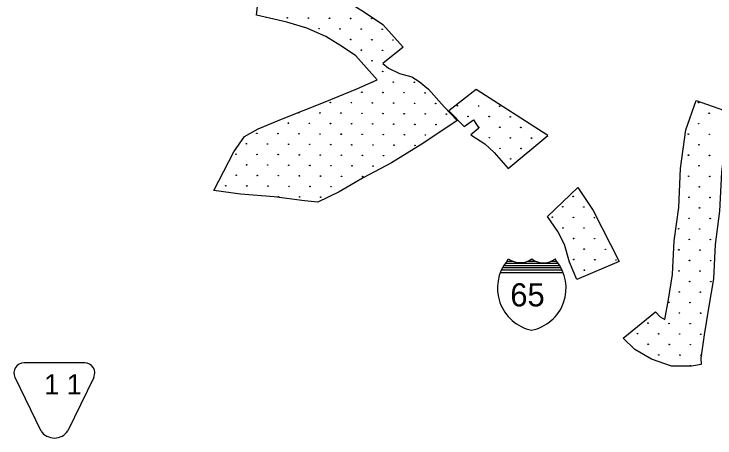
# Model space of a CAD drawing. Extents: x 1612280 to 1883141, y 560852 to 780851.
# Drawn here: x 1746855 to 1759645, y 710000 to 717744 of the extents above; entities that cross this region are included whole.
import ezdxf

# ---------------------------------------------------------------- set-up
doc = ezdxf.new("R2010")
doc.units = 0
for name, color, linetype in [('DESIGN - EROSION CONTROL - Devices', 7, 'Continuous'), ('DESIGN - ROW - Easement Linework and Patterning', 7, 'Continuous'), ('DESIGN - SCRATCH - User 1', 7, 'Continuous'), ('SURVEY - DRAINAGE - Bridge Hydraulic Data with Text', 7, 'Continuous')]:
    doc.layers.add(name, color=color, linetype=linetype)

msp = doc.modelspace()

# ---------------------------------------------------------------- linework, layer by layer
at = {"layer": 'DESIGN - EROSION CONTROL - Devices'}
for centre in [(1751842, 717674), (1751842, 717674), (1752227, 717670), (1752227, 717670), (1752611, 717666), (1752611, 717666), (1752996, 717662), (1752996, 717662), (1753380, 717659), (1753380, 717659), (1752421, 717476), (1752421, 717476), (1752805, 717472), (1752805, 717472), (1753190, 717468), (1753190, 717468), (1753574, 717465), (1753574, 717465), (1752999, 717278), (1752999, 717278), (1753384, 717274), (1753384, 717274), (1753768, 717270), (1753768, 717270), (1753194, 717084), (1753194, 717084), (1753578, 717080), (1753578, 717080), (1753388, 716890), (1753388, 716890), (1753582, 716695), (1753582, 716695), (1753776, 716501), (1753776, 716501), (1754161, 716498), (1754161, 716498), (1753201, 716315), (1753201, 716315), (1753586, 716311), (1753586, 716311), (1753970, 716307), (1753970, 716307), (1754355, 716303), (1754355, 716303), (1752626, 716128), (1752626, 716128), (1753011, 716124), (1753011, 716124), (1753395, 716120), (1753395, 716120), (1753780, 716117), (1753780, 716117), (1754164, 716113), (1754164, 716113), (1754549, 716109), (1754549, 716109), (1754946, 716068), (1754946, 716068), (1755331, 716064), (1755331, 716064), (1755715, 716060), (1755715, 716060), (1759345, 716125), (1759345, 716125), (1752051, 715941), (1752051, 715941), (1752436, 715938), (1752436, 715938), (1752820, 715934), (1752820, 715934), (1753205, 715930), (1753205, 715930), (1753589, 715926), (1753589, 715926), (1753974, 715923), (1753974, 715923), (1754358, 715919), (1754358, 715919), (1754743, 715915), (1754743, 715915), (1759539, 715931), (1759539, 715931), (1755140, 715873), (1755140, 715873), (1755525, 715870), (1755525, 715870), (1755909, 715866), (1755909, 715866), (1751861, 715751), (1751861, 715751), (1752245, 715747), (1752245, 715747), (1752630, 715743), (1752630, 715743), (1753014, 715740), (1753014, 715740), (1753399, 715736), (1753399, 715736), (1753783, 715732), (1753783, 715732), (1754168, 715728), (1754168, 715728), (1754553, 715725), (1754553, 715725), (1755334, 715679), (1755334, 715679), (1755719, 715676), (1755719, 715676), (1756103, 715672), (1756103, 715672), (1759348, 715741), (1759348, 715741), (1751286, 715564), (1751286, 715564), (1751670, 715560), (1751670, 715560), (1752055, 715557), (1752055, 715557), (1752439, 715553), (1752439, 715553), (1752824, 715549), (1752824, 715549), (1753208, 715546), (1753208, 715546), (1753593, 715542), (1753593, 715542), (1753978, 715538), (1753978, 715538), (1754362, 715534), (1754362, 715534), (1759158, 715550), (1759158, 715550), (1759542, 715546), (1759542, 715546), (1755528, 715485), (1755528, 715485), (1755913, 715481), (1755913, 715481), (1756298, 715478), (1756298, 715478), (1751095, 715374), (1751095, 715374), (1751480, 715370), (1751480, 715370), (1751864, 715366), (1751864, 715366), (1752249, 715363), (1752249, 715363), (1752634, 715359), (1752634, 715359), (1753018, 715355), (1753018, 715355), (1753403, 715351), (1753403, 715351), (1753787, 715348), (1753787, 715348), (1754172, 715344), (1754172, 715344), (1755723, 715291), (1755723, 715291), (1756107, 715287), (1756107, 715287), (1759352, 715356), (1759352, 715356), (1750905, 715183), (1750905, 715183), (1751289, 715180), (1751289, 715180), (1751674, 715176), (1751674, 715176), (1752059, 715172), (1752059, 715172), (1752443, 715168), (1752443, 715168), (1752828, 715165), (1752828, 715165), (1753212, 715161), (1753212, 715161), (1753597, 715157), (1753597, 715157), (1759162, 715166), (1759162, 715166), (1759546, 715162), (1759546, 715162), (1755917, 715097), (1755917, 715097), (1751099, 714989), (1751099, 714989), (1751484, 714986), (1751484, 714986), (1751868, 714982), (1751868, 714982), (1752253, 714978), (1752253, 714978), (1752637, 714974), (1752637, 714974), (1753022, 714971), (1753022, 714971), (1753406, 714967), (1753406, 714967), (1759356, 714972), (1759356, 714972), (1750909, 714799), (1750909, 714799), (1751293, 714795), (1751293, 714795), (1751678, 714791), (1751678, 714791), (1752062, 714788), (1752062, 714788), (1752447, 714784), (1752447, 714784), (1752831, 714780), (1752831, 714780), (1753216, 714776), (1753216, 714776), (1759165, 714781), (1759165, 714781), (1759550, 714777), (1759550, 714777), (1750718, 714608), (1750718, 714608), (1751103, 714605), (1751103, 714605), (1751487, 714601), (1751487, 714601), (1751872, 714597), (1751872, 714597), (1752256, 714593), (1752256, 714593), (1752641, 714590), (1752641, 714590), (1759360, 714587), (1759360, 714587), (1751681, 714407), (1751681, 714407), (1752066, 714403), (1752066, 714403), (1752451, 714399), (1752451, 714399), (1757058, 714413), (1757058, 714413), (1759169, 714397), (1759169, 714397), (1759554, 714393), (1759554, 714393), (1756867, 714223), (1756867, 714223), (1757252, 714219), (1757252, 714219), (1759363, 714202), (1759363, 714202), (1756677, 714033), (1756677, 714033), (1757061, 714029), (1757061, 714029), (1757446, 714025), (1757446, 714025), (1759173, 714012), (1759173, 714012), (1759557, 714008), (1759557, 714008), (1756871, 713838), (1756871, 713838), (1757256, 713835), (1757256, 713835), (1758982, 713822), (1758982, 713822), (1759367, 713818), (1759367, 713818), (1757065, 713644), (1757065, 713644), (1757450, 713641), (1757450, 713641), (1759177, 713627), (1759177, 713627), (1759561, 713624), (1759561, 713624), (1757259, 713450), (1757259, 713450), (1757644, 713446), (1757644, 713446), (1758986, 713437), (1758986, 713437), (1759371, 713433), (1759371, 713433), (1757069, 713260), (1757069, 713260), (1757453, 713256), (1757453, 713256), (1757838, 713252), (1757838, 713252), (1759180, 713243), (1759180, 713243), (1759565, 713239), (1759565, 713239), (1757263, 713066), (1757263, 713066), (1758990, 713052), (1758990, 713052), (1759374, 713049), (1759374, 713049), (1759184, 712858), (1759184, 712858), (1759569, 712855), (1759569, 712855), (1758994, 712668), (1758994, 712668), (1759378, 712664), (1759378, 712664), (1758803, 712478), (1758803, 712478), (1759188, 712474), (1759188, 712474), (1758997, 712283), (1758997, 712283), (1759382, 712280), (1759382, 712280), (1758422, 712097), (1758422, 712097), (1758807, 712093), (1758807, 712093), (1759192, 712089), (1759192, 712089), (1758232, 711906), (1758232, 711906), (1758617, 711903), (1758617, 711903), (1759001, 711899), (1759001, 711899), (1759386, 711895), (1759386, 711895), (1758426, 711712), (1758426, 711712), (1758811, 711708), (1758811, 711708), (1759195, 711705), (1759195, 711705), (1758620, 711518), (1758620, 711518), (1759005, 711514), (1759005, 711514), (1759199, 711320), (1759199, 711320)]:
    msp.add_circle(centre, 5.28, dxfattribs=at)
for centre, start, end in [((1751457, 717677), 5.3165, 148.9686), ((1752615, 717282), 43.411, 73.0323), ((1753391, 716505), 256.2081, 331.4732), ((1758979, 714206), 304.2192, 42.441), ((1759389, 711511), 40.3396, 303.8183), ((1758814, 711324), 2.3169, 139.8877)]:
    msp.add_arc(centre, 5.28, start, end, dxfattribs=at)
at = {"layer": 'DESIGN - ROW - Easement Linework and Patterning'}
for p, q in [((1748144, 711373), (1747039, 711373)), ((1748144, 711373), (1747039, 711373)), ((1747348, 710127), (1746873, 711107)), ((1747348, 710127), (1746873, 711107)), ((1748310, 711107), (1747837, 710130)), ((1748310, 711107), (1747837, 710130))]:
    msp.add_line(p, q, dxfattribs=at)
for centre, radius, start, end in [((1747039, 711188), 185, 90.0012, 205.8236), ((1747039, 711188), 185, 90.0012, 205.8236), ((1748144, 711188), 185, 334.1799, 90.0012), ((1748144, 711188), 185, 334.1799, 90.0012), ((1747591, 710298), 298, 215.137, 325.5451), ((1747591, 710298), 298, 215.137, 325.5451)]:
    msp.add_arc(centre, radius, start, end, dxfattribs=at)
at = {"layer": 'DESIGN - SCRATCH - User 1'}
for points in [[(1751278, 717720), (1751429, 719122), (1752413, 719088), (1752432, 718904), (1753280, 718942), (1753271, 719214), (1753213, 719723), (1753140, 720252), (1753072, 720601), (1752970, 721018), (1752868, 721309), (1752762, 721542), (1752527, 721698)], [(1751278, 717720), (1751429, 719122), (1752413, 719088), (1752432, 718904), (1753280, 718942), (1753271, 719214), (1753213, 719723), (1753140, 720252), (1753072, 720601), (1752970, 721018), (1752868, 721309), (1752762, 721542), (1752527, 721698)], [(1752537, 718158), (1752897, 717995), (1753253, 717775), (1753586, 717554), (1753957, 717138)], [(1752537, 718158), (1752897, 717995), (1753253, 717775), (1753586, 717554), (1753957, 717138)], [(1754940, 715799), (1754317, 715382), (1753745, 715023), (1753227, 714751), (1752786, 714494), (1752398, 714305), (1752156, 714334), (1751603, 714402), (1750988, 714451), (1750503, 714519), (1750866, 715227), (1751060, 715508), (1751307, 715644), (1751763, 715838), (1752534, 716143), (1753110, 716376), (1753484, 716541), (1753091, 716983), (1752849, 717143), (1752543, 717332), (1752199, 717487), (1751831, 717594), (1751278, 717720)], [(1754940, 715799), (1754317, 715382), (1753745, 715023), (1753227, 714751), (1752786, 714494), (1752398, 714305), (1752156, 714334), (1751603, 714402), (1750988, 714451), (1750503, 714519), (1750866, 715227), (1751060, 715508), (1751307, 715644), (1751763, 715838), (1752534, 716143), (1753110, 716376), (1753484, 716541), (1753091, 716983), (1752849, 717143), (1752543, 717332), (1752199, 717487), (1751831, 717594), (1751278, 717720)], [(1753957, 717138), (1753583, 716842)], [(1753957, 717138), (1753583, 716842)], [(1753583, 716842), (1753688, 716755), (1753891, 716656), (1754113, 716596), (1754250, 716513), (1754415, 716372), (1754704, 716046), (1754940, 715799)], [(1753583, 716842), (1753688, 716755), (1753891, 716656), (1754113, 716596), (1754250, 716513), (1754415, 716372), (1754704, 716046), (1754940, 715799)], [(1755285, 716368), (1754791, 715976)], [(1755285, 716368), (1754791, 715976)], [(1756594, 715527), (1755285, 716368)], [(1756594, 715527), (1755285, 716368)], [(1759113, 715631), (1759304, 716162)], [(1759113, 715631), (1759304, 716162)], [(1759304, 716162), (1760216, 715840)], [(1759304, 716162), (1760216, 715840)], [(1754791, 715976), (1755069, 715692), (1755238, 715809), (1755335, 715658), (1755190, 715537)], [(1754791, 715976), (1755069, 715692), (1755238, 715809), (1755335, 715658), (1755190, 715537)], [(1755190, 715537), (1755447, 715372), (1755616, 715212), (1755873, 714921), (1756594, 715527)], [(1755190, 715537), (1755447, 715372), (1755616, 715212), (1755873, 714921), (1756594, 715527)], [(1758733, 712165), (1758797, 712531), (1758870, 712987), (1758902, 713602), (1758983, 714208), (1759015, 714922), (1759113, 715631)], [(1758733, 712165), (1758797, 712531), (1758870, 712987), (1758902, 713602), (1758983, 714208), (1759015, 714922), (1759113, 715631)], [(1759784, 715010), (1759763, 714853), (1759730, 714142), (1759650, 713533), (1759617, 712908), (1759536, 712406), (1759445, 711884), (1759386, 711458), (1759392, 711341)], [(1759784, 715010), (1759763, 714853), (1759730, 714142), (1759650, 713533), (1759617, 712908), (1759536, 712406), (1759445, 711884), (1759386, 711458), (1759392, 711341)], [(1756591, 714048), (1757140, 714575)], [(1756591, 714048), (1757140, 714575)], [(1757140, 714575), (1757424, 714153), (1757897, 713226)], [(1757140, 714575), (1757424, 714153), (1757897, 713226)], [(1757897, 713226), (1757126, 712894), (1756990, 713209), (1756898, 713534), (1756777, 713772), (1756591, 714048)], [(1757897, 713226), (1757126, 712894), (1756990, 713209), (1756898, 713534), (1756777, 713772), (1756591, 714048)], [(1757972, 711826), (1758558, 712302)], [(1757972, 711826), (1758558, 712302)], [(1758558, 712302), (1758646, 712216), (1758733, 712165)], [(1758558, 712302), (1758646, 712216), (1758733, 712165)], [(1758486, 711438), (1758185, 711618), (1757972, 711826)], [(1758486, 711438), (1758185, 711618), (1757972, 711826)], [(1759392, 711341), (1759218, 711312), (1758854, 711312), (1758486, 711438)], [(1759392, 711341), (1759218, 711312), (1758854, 711312), (1758486, 711438)]]:
    msp.add_lwpolyline(points, dxfattribs=at)
at = {"layer": 'SURVEY - DRAINAGE - Bridge Hydraulic Data with Text'}
for p, q in [((1755847, 713229), (1755954, 713229)), ((1755847, 713229), (1755954, 713229)), ((1756223, 713229), (1756370, 713229)), ((1756223, 713229), (1756370, 713229)), ((1756656, 713229), (1756756, 713229)), ((1756656, 713229), (1756756, 713229)), ((1755772, 713112), (1756828, 713112)), ((1755772, 713112), (1756828, 713112)), ((1755798, 713151), (1756804, 713151)), ((1755798, 713151), (1756804, 713151)), ((1755822, 713196), (1756779, 713196)), ((1755822, 713196), (1756779, 713196)), ((1755731, 713021), (1756868, 713021)), ((1755731, 713021), (1756868, 713021)), ((1755751, 713072), (1756848, 713072)), ((1755751, 713072), (1756848, 713072))]:
    msp.add_line(p, q, dxfattribs=at)
for points in [[(1755851, 713235), (1755874, 713274)], [(1755851, 713235), (1755874, 713274)], [(1756752, 713232), (1756732, 713272)], [(1756752, 713232), (1756732, 713272)]]:
    msp.add_lwpolyline(points, dxfattribs=at)
for centre, radius, start, end in [((1756462, 712740), 787, 140.9901, 258.178), ((1756462, 712740), 787, 140.9901, 258.178), ((1756090, 713573), 370, 234.1647, 305.144), ((1756090, 713573), 370, 234.1647, 305.144), ((1756147, 712737), 782, 281.2226, 39.2925), ((1756147, 712737), 782, 281.2226, 39.2925), ((1756517, 713548), 350, 232.3625, 307.9876), ((1756517, 713548), 350, 232.3625, 307.9876)]:
    msp.add_arc(centre, radius, start, end, dxfattribs=at)

# ---------------------------------------------------------------- texts
at = {"layer": 'DESIGN - ROW - Easement Linework and Patterning'}
msp.add_text('1 1', height=369.6, rotation=0.0012, dxfattribs=at).set_placement((1747404, 710795))
msp.add_text('1 1', height=369.6, rotation=0.0012, dxfattribs=at).set_placement((1747404, 710795))
at = {"layer": 'SURVEY - DRAINAGE - Bridge Hydraulic Data with Text'}
msp.add_text('65', height=422.4, rotation=0.0013, dxfattribs=at).set_placement((1755910, 712404))
msp.add_text('65', height=422.4, rotation=0.0013, dxfattribs=at).set_placement((1755910, 712404))

doc.saveas('drawing.dxf')
